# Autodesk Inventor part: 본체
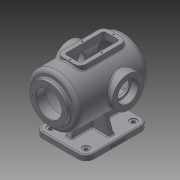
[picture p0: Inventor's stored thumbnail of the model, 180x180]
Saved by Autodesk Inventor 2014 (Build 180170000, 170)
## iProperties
Created: 2021-11
Part Number: 본체
Material: Generic
Document SubType Name: Modeling
Designer: kb542-02
Density: 1 g/cm^3
Appearance: Default
Author: kb542-02
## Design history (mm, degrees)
sketch "스케치1"
  geometry: L1 (0, 0)-(210, 0); L2 (0, 32.5)-(0, 47.5); L3 (0, 47.5)-(10, 47.5); L4 (10, 47.5)-(10, 65); L5 (10, 65)-(185.993, 65); L6 (0, 32.5)-(25, 32.5); L7 (25, 32.5)-(25, 55); L8 (25, 55)-(181.239, 55); L9 (200, 0)-(210, 0); A1 r 100 centre (110, 0) between (210, 0) and (185.993, 65); A2 r 90 centre (110, 0) between (200, 0) and (181.239, 55)
  constraints: 18 end point, 4 point on circle, 3 parallel, 3 perpendicular, 2 centre point, 2 horizontal, 1 coincident, 1 collinear, 1 horizontal alignment, 1 point on line, 1 vertical alignment
  dimensions: "d0" = 100 radius of A1; "d1" = 65 diameter of L6 L1; "d2" = 95 diameter of L3 L1; "d3" = 130 diameter of L5 L1; "d4" = 110 diameter of L8 L1; "d5" = 210 distance from line of L1.end L2; "d7" = 25 distance between parallel lines of L7 L2; "d8" = 10 radial gap between concentric circles of A1 A2; "d137" = 10 distance between parallel lines of L4 L2
revolve "회전1" sketch "스케치1" stored, may be unused: angle "d6" = 90 deg
node "작업 평면1"
sketch "스케치2"
  geometry: L1 (30, 65)-(190, 65); L2 (190, 65)-(190, -65); L3 (190, -65)-(30, -65); L4 (30, -65)-(30, 65); L5 (0, -47.5)-(0, 47.5) reference; 3 further points
  constraints: 8 end point, 2 midpoint, 2 parallel, 1 horizontal, 1 horizontal alignment, 1 perpendicular
  dimensions: "d10" = 130 distance between parallel lines of L3 L1; "d11" = 160 distance between parallel lines of L4 L2; "d12" = 30 distance between parallel lines of L5 L4
extrude "돌출1" join sketch "스케치2" distance "d13" = 14; taper "d14" = 0 deg
fillet "모깎기1" dims "d15" = 20
sketch "스케치3"
  geometry: A1 r 20 centre (170, 45) between (190, 45) and (170, 65) reference; A2 r 20 centre (50, 45) between (50, 65) and (30, 45) reference; A3 r 20 centre (50, -45) between (30, -45) and (50, -65) reference; A4 r 20 centre (170, -45) between (170, -65) and (190, -45) reference; 5 further points
  constraints: 4 coincident
hole "구멍1" sketch "스케치3" at (50, 45), (170, 45), (170, -45), (50, -45) diameter "d16" = 9; stored, may be unused: countersink angle "d20" = 90 deg, drill point angle "d22" = 118 deg; dims "d17" = 6, "d18" = 18, "d19" = 2, "d21" = 8
sketch "스케치4"
  geometry: L1 (170, 65)-(50, 65) reference; L2 (190, -45)-(190, 45) reference; L3 (103, 50)-(117, 50); L4 (117, 50)-(117, -50); L5 (117, -50)-(103, -50); L6 (103, -50)-(103, 50); L7 (50, 7)-(170, 7); L8 (170, 7)-(170, -7); L9 (170, -7)-(50, -7); L10 (50, -7)-(50, 7); 7 further points
  constraints: 16 end point, 6 midpoint, 4 parallel, 2 horizontal, 2 horizontal alignment, 2 perpendicular, 2 vertical alignment
  dimensions: "d23" = 14 distance between parallel lines of L4 L6; "d24" = 14 distance between parallel lines of L9 L7; "d25" = 120 distance between parallel lines of L8 L10; "d26" = 100 distance between parallel lines of L5 L3
extrude "돌출3" join sketch "스케치4" stored distance "d29" = 14; taper "d30" = 0 deg
feature "면 기울기1" dims angle "d31" = 20 deg
sketch "스케치8" dims "d60" = 80
  geometry: L1 (0, 0)-(0, 40); C1 r 47.5 at (0, 0) reference; 1 further point
  constraints: 2 coincident, 2 end point, 1 vertical, 1 vertical alignment, 2 other
hole "구멍4" sketch "스케치8" at (0, 40) diameter "d61" = 3.242; stored, may be unused: countersink angle "d65" = 90 deg, drill point angle "d67" = 118 deg; dims "d62" = 11, "d63" = 52, "d64" = 18, "d66" = 13
node "작업 평면3"
sketch "스케치9"
  geometry: L1 (50, 30)-(170, 30); L2 (170, 30)-(170, -30); L3 (170, -30)-(50, -30); L4 (50, -30)-(50, 30); L5 (0, -47.5)-(0, 47.5) reference; 3 further points
  constraints: 8 end point, 2 midpoint, 2 parallel, 1 horizontal, 1 horizontal alignment, 1 perpendicular
  dimensions: "d72" = 50 distance between parallel lines of L5 L4; "d73" = 120 distance between parallel lines of L2 L4; "d74" = 60 distance between parallel lines of L3 L1
extrude "돌출5" join sketch "스케치9" stored distance "d75" = 150; taper "d76" = 0 deg
fillet "모깎기2" dims "d77" = 15
sketch "스케치10"
  geometry: L1 (170, 15)-(170, -15) reference; L2 (65, 30)-(155, 30) reference; L3 (50, -15)-(50, 15) reference; L4 (155, -30)-(65, -30) reference; L5 (160, 15)-(160, -15); L6 (155, -20)-(65, -20); L7 (60, -15)-(60, 15); L8 (65, 20)-(155, 20); A1 r 15 centre (155, -15) between (155, -30) and (170, -15) reference; A2 r 15 centre (155, 15) between (170, 15) and (155, 30) reference; A3 r 15 centre (65, 15) between (65, 30) and (50, 15) reference; A4 r 15 centre (65, -15) between (50, -15) and (65, -30) reference; A5 r 5 centre (155, 15) between (160, 15) and (155, 20); A6 r 5 centre (155, -15) between (155, -20) and (160, -15); A7 r 5 centre (65, -15) between (60, -15) and (65, -20); A8 r 5 centre (65, 15) between (65, 20) and (60, 15); 1 further point
  constraints: 8 end point, 8 point on circle, 4 centre point, 7 other
  dimensions: "d78" = 10 distance between parallel lines of L2 L8
extrude "돌출6" cut sketch "스케치10" stored distance "d79" = 150; taper "d80" = 0 deg
sketch "스케치11"
  geometry: L1 (127, 75)-(127, -75); L2 (110, 25)-(110, -25); 5 further points
  constraints: 4 end point, 4 horizontal alignment, 2 midpoint, 1 parallel, 1 vertical alignment
  dimensions: "d81" = 55 horizontal distance of point (165, 0) L2.start; "d82" = 55 horizontal distance of point (55, 0) L2.start; "d83" = 17 distance from line of L2.start L1; "d84" = 50 distance of L2.end L2.start; "d118" = 150 distance of L1.start L1.end
hole "구멍5" sketch "스케치11" at (110, 25), (110, -25), (165, 0), (55, 0) diameter "d85" = 3.242; stored, may be unused: countersink angle "d89" = 90 deg, drill point angle "d91" = 118 deg; dims "d86" = 9, "d87" = 52, "d88" = 18, "d90" = 11
node "작업 평면4"
sketch "스케치12"
  geometry: L1 (0, -47.5)-(0, 47.5) reference; C1 r 40 at (127, 0); 1 further point
  constraints: 1 centre point, 1 horizontal alignment
  dimensions: "d93" = 80 diameter of C1; "d94" = 127 distance from line of L1 C1.centre
extrude "돌출7" join sketch "스케치12" stored distance "d95" = 150; taper "d96" = 0 deg
sketch "스케치13" dims "d97" = 65
  geometry: L1 (0, 0)-(0, 32.5); C1 r 40 at (0, 0) reference; 2 further points
  constraints: 2 coincident, 2 end point, 1 vertical, 1 vertical alignment, 2 other
hole "구멍6" sketch "스케치13" at (0, 32.5) diameter "d98" = 3.242; stored, may be unused: countersink angle "d102" = 90 deg, drill point angle "d104" = 118 deg; dims "d99" = 11, "d100" = 52, "d101" = 18, "d103" = 13
fillet "모깎기3" dims "d111" = 3, "d112" = 10
fillet "모깎기4" dims "d113" = 3
fillet "모깎기5" dims "d114" = 3
node "작업 평면5"
sketch "스케치16"
  geometry: L1 (120, 0)-(0, 0) reference; 3 further points
  constraints: 1 midpoint, 1 vertical alignment, 1 other
  dimensions: "d120" = 5 distance of point (60, 0) point (60, 5)
feature "엠보싱1" sketch "스케치16" dims "d0" = 100, "d1" = 65, "d2" = 95, "d3" = 130, "d4" = 110, "d5" = 210, "d7" = 25, "d8" = 10, "d10" = 130, "d11" = 160, "d12" = 30, "d121" = 0.5, "d122" = 0, "d137" = 10
hole "구멍7" diameter "d125" = 42; stored, may be unused: countersink angle "d129" = 90 deg, drill point angle "d131" = 118 deg; dims "d123" = 10, "d124" = 10, "d126" = 11, "d127" = 52, "d128" = 18, "d130" = 40
fillet "모깎기6" dims "d132" = 3
fillet "모깎기7" dims "d133" = 0.3
chamfer "모따기2" distance "d134" = 1; stored, may be unused: second distance "d135" = 2, angle "d136" = 45 deg
node "솔리드1"
pattern_circular "원형 패턴2" dims angle "d69" = 360 deg
pattern_circular "원형 패턴3" dims angle "d106" = 360 deg
mirror "대칭3"
mirror "대칭4"
other parameters: "d9" = -114, "d92" = -75, "d119" = 27.25
